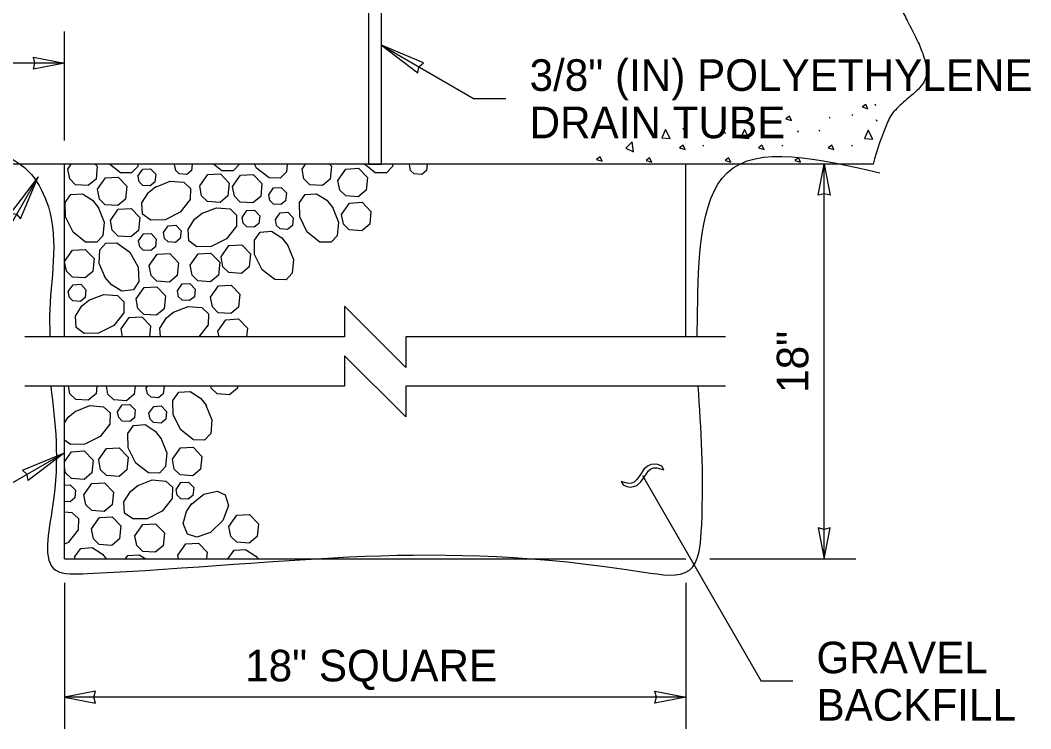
# Model space of a CAD drawing. Extents: x 99862 to 103151, y 100000 to 117076.
# Drawn here: x 101760 to 102272, y 109621 to 109980 of the extents above; entities that cross this region are included whole.
import ezdxf

# ---------------------------------------------------------------- set-up
doc = ezdxf.new("R2010")
doc.units = 0
for name, color, linetype in [('Level 11', 7, 'Continuous'), ('Level 14', 7, 'Continuous'), ('Level 15', 7, 'Continuous'), ('Level 18', 7, 'Continuous'), ('Level 20', 7, 'Continuous'), ('Level 29', 7, 'Continuous')]:
    doc.layers.add(name, color=color, linetype=linetype)

msp = doc.modelspace()

# ---------------------------------------------------------------- linework, layer by layer
at = {"layer": 'Level 11'}
for p, q in [((102191.96, 109906.89), (101636.86, 109906.89)), ((101782.16, 109819.39), (101782.16, 109906.89)), ((101936.38, 109906.89), (101942.94, 109906.89)), ((102097.16, 109819.39), (102097.16, 109906.89)), ((101782.16, 109706.89), (101782.16, 109794.39)), ((101782.16, 109706.89), (102097.16, 109706.89))]:
    msp.add_line(p, q, dxfattribs=at)
msp.add_spline([(102191.96, 110071.89), (102193.22, 110069.54), (102195.32, 110067.28), (102200.74, 110062.92), (102205.63, 110058.55), (102207.07, 110056.29), (102207.4, 110055.12), (102207.42, 110053.93), (102207.2, 110052.86), (102205.67, 110049.64), (102202.39, 110045.28), (102198.86, 110040.8), (102197.41, 110038.5), (102196.37, 110036.15), (102195.3, 110033.02), (102194.16, 110029.73), (102192.08, 110022.91), (102191.05, 110016.09), (102191.21, 110012.82), (102191.5, 110011.23), (102191.96, 110009.7), (102195.13, 110002.95), (102199.2, 109996.43), (102203.51, 109989.93), (102205.55, 109986.62), (102207.4, 109983.24), (102209.24, 109979.65), (102214.83, 109968.51), (102217.73, 109961.06), (102218.67, 109957.4), (102218.97, 109955.61), (102219.08, 109954.72), (102219.16, 109953.84), (102216.82, 109947.2), (102210.8, 109941.21), (102204, 109935.1), (102201.21, 109931.76), (102199.31, 109928.11), (102191.96, 109906.89)], degree=3, dxfattribs=at)
at = {"layer": 'Level 14'}
for p, q in [((101936.38, 109906.89), (101936.38, 110019.39)), ((101942.94, 109906.89), (101942.94, 110019.39))]:
    msp.add_line(p, q, dxfattribs=at)
at = {"layer": 'Level 15'}
for p, q in [((101782.16, 109918.89), (101782.16, 109974.04)), ((101942.94, 109967.12), (101989.9, 109940.01)), ((101782.16, 109958.04), (101677.98, 109958.04)), ((102005.9, 109940.01), (101989.9, 109940.01)), ((102167.16, 109706.89), (102167.16, 109906.89)), ((101768.82, 109900.41), (101734.16, 109840.38)), ((101782.16, 109760.64), (101725.87, 109728.14)), ((102079.51, 109754.79), (102077.98, 109754.14)), ((102081.12, 109754.97), (102079.51, 109754.79)), ((102082.87, 109754.7), (102081.12, 109754.97)), ((102084.89, 109753.95), (102082.87, 109754.7)), ((102076.05, 109752.6), (102073.78, 109749.2)), ((102074.32, 109745.95), (102076.84, 109749.57)), ((102077.98, 109754.14), (102076.05, 109752.6)), ((102076.84, 109749.57), (102078.22, 109751.56)), ((102078.22, 109751.56), (102079.38, 109752.51)), ((102079.38, 109752.51), (102080.72, 109752.99)), ((102080.72, 109752.99), (102082.37, 109753.05)), ((102082.37, 109753.05), (102085.94, 109752.12)), ((102085.94, 109752.12), (102084.89, 109753.95)), ((102066.56, 109745.48), (102064.25, 109746.22)), ((102064.25, 109746.22), (102065.31, 109744.39)), ((102065.31, 109744.39), (102067.14, 109743.62)), ((102068.27, 109745.21), (102066.56, 109745.48)), ((102069.63, 109745.36), (102068.27, 109745.21)), ((102070.86, 109745.85), (102069.63, 109745.36)), ((102072.32, 109747.11), (102070.86, 109745.85)), ((102072.23, 109744.2), (102074.32, 109745.95)), ((102073.78, 109749.2), (102072.32, 109747.11)), ((102075.14, 109749.18), (102135.28, 109645.01)), ((102067.14, 109743.62), (102068.91, 109743.33)), ((102068.91, 109743.33), (102070.61, 109743.53)), ((102070.61, 109743.53), (102072.23, 109744.2)), ((102109.16, 109706.89), (102183.16, 109706.89)), ((101782.16, 109694.89), (101782.16, 109620.89)), ((102097.16, 109694.89), (102097.16, 109620.89)), ((102151.28, 109645.01), (102135.28, 109645.01)), ((102097.16, 109636.89), (101782.16, 109636.89))]:
    msp.add_line(p, q, dxfattribs=at)
for points in [[(101942.94, 109967.12), (101961.22, 109953.12), (101961.8, 109956.23), (101964.21, 109958.29)], [(101782.16, 109958.04), (101766.44, 109954.96), (101767.17, 109958.04), (101766.44, 109961.12)], [(102167.16, 109906.89), (102170.25, 109891.17), (102167.16, 109891.89), (102164.08, 109891.17)], [(101768.82, 109900.41), (101754.82, 109882.13), (101757.93, 109881.56), (101759.99, 109879.15)], [(101782.16, 109760.64), (101763.88, 109746.64), (101763.31, 109749.75), (101760.9, 109751.81)], [(102167.16, 109706.89), (102170.25, 109722.62), (102167.16, 109721.89), (102164.08, 109722.62)], [(101782.16, 109636.89), (101797.89, 109633.81), (101797.16, 109636.89), (101797.89, 109639.97)], [(102097.16, 109636.89), (102081.44, 109633.81), (102082.17, 109636.89), (102081.44, 109639.97)]]:
    msp.add_lwpolyline(points, close=True, dxfattribs=at)
for points in [[(102117.16, 109819.39), (101955.15, 109819.39), (101955.15, 109803.9), (101924.18, 109834.88), (101924.18, 109819.39), (101762.16, 109819.39)], [(102117.16, 109794.39), (101955.15, 109794.39), (101955.15, 109778.9), (101924.18, 109809.88), (101924.18, 109794.39), (101762.16, 109794.39)]]:
    msp.add_lwpolyline(points, dxfattribs=at)
at = {"layer": 'Level 18'}
for p, q in [((102193.43, 109936.43), (102193.07, 109937.23)), ((102170.21, 109929.93), (102169.86, 109930.73)), ((102181.47, 109932.08), (102181.12, 109931.55)), ((102194.11, 109928.49), (102193.75, 109929.29)), ((102096.12, 109924.27), (102095.76, 109925.07)), ((102154.19, 109922.95), (102153.84, 109923.75)), ((102164.79, 109924.17), (102164.43, 109923.64)), ((102117.16, 109922.23), (102116.81, 109923.03)), ((102106.06, 109916.55), (102105.71, 109916.01)), ((102146.06, 109916.55), (102145.71, 109916.01)), ((102181.44, 109916.55), (102181.08, 109916.01))]:
    msp.add_line(p, q, dxfattribs=at)
for points in [[(102189.36, 109934.96), (102188.3, 109937.18), (102186.52, 109935.85), (102189.36, 109934.96)], [(102150.66, 109928.93), (102149.6, 109931.15), (102147.82, 109929.82), (102150.66, 109928.93)], [(102089.15, 109919.83), (102086.75, 109924.36), (102084.89, 109920.19), (102089.06, 109919.83)], [(102129.15, 109919.83), (102126.75, 109924.36), (102124.89, 109920.19), (102129.06, 109919.83)], [(102191.89, 109919.51), (102189.49, 109924.04), (102187.63, 109919.86), (102191.8, 109919.51)], [(102070.61, 109913.12), (102069.91, 109918.19), (102066.73, 109914.91), (102070.53, 109913.15)], [(102096.74, 109914.24), (102095.67, 109916.46), (102093.9, 109915.12), (102096.74, 109914.24)], [(102136.74, 109914.24), (102135.67, 109916.46), (102133.9, 109915.12), (102136.74, 109914.24)], [(102172.11, 109914.24), (102171.05, 109916.46), (102169.27, 109915.12), (102172.11, 109914.24)], [(102054.74, 109908.35), (102053.67, 109910.57), (102051.89, 109909.24), (102054.74, 109908.35)], [(102079.81, 109907.89), (102078.74, 109910.11), (102076.97, 109908.78), (102079.81, 109907.89)], [(102119.81, 109907.89), (102118.74, 109910.11), (102116.97, 109908.78), (102119.81, 109907.89)], [(102155.18, 109907.89), (102154.12, 109910.11), (102152.34, 109908.78), (102155.18, 109907.89)], [(101783.9, 109904.37), (101785.67, 109906.89)], [(101797.83, 109906.89), (101798.85, 109905.83), (101798.2, 109899.32), (101794.22, 109896.02), (101787.86, 109896.48), (101784.87, 109899.38), (101783.9, 109904.36)], [(101819.44, 109906.89), (101819.34, 109905.76), (101816.21, 109902.47), (101810.59, 109902.57), (101805.07, 109906.89)], [(101819.47, 109900.87), (101821.89, 109904.31), (101825.76, 109904.53), (101828.44, 109901.75), (101828.06, 109897.84), (101825.67, 109895.86), (101821.85, 109896.13), (101820.06, 109897.87), (101819.48, 109900.87)], [(101838, 109906.69), (101838.15, 109906.89)], [(101846.91, 109906.89), (101846.59, 109903.66), (101844.2, 109901.68), (101840.38, 109901.95), (101838.59, 109903.69), (101838.01, 109906.69)], [(101870.77, 109906.89), (101870.76, 109906.74), (101867.62, 109903.44), (101862, 109903.55), (101857.73, 109906.89)], [(101895, 109906.89), (101894.67, 109903.08), (101891.54, 109899.78), (101885.92, 109899.89), (101879.52, 109904.89), (101878.52, 109906.89)], [(101902.62, 109904.37), (101904.39, 109906.89)], [(101916.55, 109906.89), (101917.57, 109905.83), (101916.92, 109899.32), (101912.94, 109896.02), (101906.58, 109896.48), (101903.59, 109899.38), (101902.62, 109904.36)], [(101920.75, 109898.67), (101924.79, 109904.41), (101931.23, 109904.78), (101935.7, 109900.13), (101935.06, 109893.63), (101931.08, 109890.32), (101924.72, 109890.78), (101921.73, 109893.68), (101920.76, 109898.67)], [(101948.58, 109906.89), (101948.48, 109905.76), (101945.35, 109902.47), (101939.73, 109902.57), (101934.21, 109906.89)], [(101957.04, 109906.69), (101957.18, 109906.89)], [(101965.94, 109906.89), (101965.62, 109903.66), (101963.23, 109901.68), (101959.41, 109901.95), (101957.62, 109903.69), (101957.04, 109906.69)], [(102076.57, 109906.69), (102076.72, 109906.89)], [(101798.91, 109894.21), (101802.94, 109899.95), (101809.38, 109900.32), (101813.86, 109895.67), (101813.21, 109889.17), (101809.24, 109885.86), (101802.88, 109886.32), (101799.88, 109889.22), (101798.91, 109894.21)], [(101828.26, 109895.3), (101835.8, 109898.29), (101842.74, 109897.69), (101846.03, 109894.56), (101845.93, 109888.94), (101840.92, 109882.55), (101833.2, 109878.68), (101825.92, 109878.55), (101821.81, 109881.47), (101821.43, 109887.27), (101824.75, 109892.45), (101828.56, 109895.49)], [(101850.76, 109895.83), (101854.79, 109901.57), (101861.23, 109901.93), (101865.71, 109897.29), (101865.06, 109890.79), (101861.08, 109887.48), (101854.72, 109887.94), (101851.73, 109890.84), (101850.76, 109895.82)], [(101867.35, 109895.58), (101871.38, 109901.32), (101877.82, 109901.69), (101882.3, 109897.04), (101881.66, 109890.54), (101877.67, 109887.23), (101871.32, 109887.69), (101868.33, 109890.59), (101867.35, 109895.58)], [(101885.71, 109891.4), (101888.12, 109894.84), (101891.99, 109895.06), (101894.68, 109892.28), (101894.29, 109888.38), (101891.9, 109886.39), (101888.08, 109886.67), (101886.29, 109888.41), (101885.71, 109891.4)], [(101799.31, 109885.1), (101802.3, 109877.56), (101801.7, 109870.62), (101798.57, 109867.33), (101792.94, 109867.43), (101786.55, 109872.44), (101782.69, 109880.16), (101782.56, 109887.44), (101785.47, 109891.54), (101791.27, 109891.93), (101796.46, 109888.61), (101799.5, 109884.8)], [(101918.03, 109885.1), (101921.02, 109877.56), (101920.42, 109870.62), (101917.29, 109867.33), (101911.66, 109867.43), (101905.27, 109872.44), (101901.41, 109880.16), (101901.28, 109887.44), (101904.19, 109891.54), (101910, 109891.93), (101915.18, 109888.61), (101918.22, 109884.8)], [(101805.46, 109878.38), (101809.49, 109884.12), (101815.94, 109884.49), (101820.41, 109879.85), (101819.76, 109873.34), (101815.79, 109870.03), (101809.43, 109870.49), (101806.43, 109873.39), (101805.46, 109878.38)], [(101851.67, 109881.82), (101859.22, 109884.81), (101866.15, 109884.21), (101869.44, 109881.08), (101869.34, 109875.46), (101864.34, 109869.06), (101856.61, 109865.2), (101849.33, 109865.07), (101845.23, 109867.99), (101844.84, 109873.79), (101848.16, 109878.98), (101851.97, 109882.01)], [(101872.18, 109879.91), (101874.6, 109883.35), (101878.47, 109883.57), (101881.15, 109880.79), (101880.77, 109876.88), (101878.38, 109874.9), (101874.56, 109875.18), (101872.77, 109876.92), (101872.19, 109879.91)], [(101922.57, 109881.46), (101926.61, 109887.2), (101933.05, 109887.56), (101937.52, 109882.92), (101936.88, 109876.42), (101932.9, 109873.11), (101926.54, 109873.57), (101923.55, 109876.47), (101922.58, 109881.46)], [(101889.11, 109878.87), (101891.53, 109882.31), (101895.39, 109882.53), (101898.08, 109879.74), (101897.69, 109875.84), (101895.31, 109873.86), (101891.49, 109874.13), (101889.69, 109875.87), (101889.11, 109878.86)], [(101832.32, 109872.25), (101834.74, 109875.69), (101838.6, 109875.91), (101841.29, 109873.13), (101840.9, 109869.22), (101838.51, 109867.24), (101834.7, 109867.51), (101832.9, 109869.25), (101832.32, 109872.25)], [(101895.2, 109866.07), (101898.2, 109858.52), (101897.6, 109851.59), (101894.47, 109848.29), (101888.84, 109848.4), (101882.45, 109853.4), (101878.59, 109861.13), (101878.46, 109868.41), (101881.37, 109872.51), (101887.17, 109872.9), (101892.36, 109869.57), (101895.4, 109865.76)], [(101819.78, 109868.09), (101822.2, 109871.53), (101826.07, 109871.75), (101828.75, 109868.97), (101828.37, 109865.06), (101825.98, 109863.08), (101822.16, 109863.35), (101820.37, 109865.09), (101819.79, 109868.09)], [(101782.29, 109857.6), (101786.33, 109863.34), (101792.77, 109863.71), (101797.24, 109859.07), (101796.6, 109852.56), (101792.62, 109849.25), (101786.26, 109849.71), (101783.27, 109852.61), (101782.3, 109857.6)], [(101803.07, 109849.15), (101799.81, 109856.58), (101800.16, 109863.53), (101803.17, 109866.93), (101808.8, 109867.03), (101815.36, 109862.26), (101819.5, 109854.68), (101819.89, 109847.41), (101817.12, 109843.21), (101811.34, 109842.61), (101806.04, 109845.75), (101802.86, 109849.45)], [(101861.55, 109859.92), (101865.58, 109865.66), (101872.03, 109866.03), (101876.5, 109861.38), (101875.86, 109854.88), (101871.88, 109851.57), (101865.52, 109852.03), (101862.53, 109854.93), (101861.56, 109859.92)], [(101825.1, 109855.48), (101829.13, 109861.21), (101835.57, 109861.58), (101840.05, 109856.94), (101839.4, 109850.43), (101835.42, 109847.12), (101829.06, 109847.59), (101826.07, 109850.49), (101825.1, 109855.47)], [(101845.91, 109855.71), (101849.94, 109861.45), (101856.38, 109861.82), (101860.86, 109857.18), (101860.21, 109850.67), (101856.23, 109847.36), (101849.87, 109847.82), (101846.88, 109850.72), (101845.91, 109855.71)], [(101784.13, 109842.36), (101786.55, 109845.8), (101790.42, 109846.02), (101793.1, 109843.24), (101792.71, 109839.33), (101790.33, 109837.35), (101786.51, 109837.62), (101784.72, 109839.37), (101784.13, 109842.36)], [(101818.48, 109838.67), (101822.52, 109844.41), (101828.95, 109844.78), (101833.43, 109840.14), (101832.79, 109833.63), (101828.81, 109830.32), (101822.45, 109830.79), (101819.46, 109833.69), (101818.48, 109838.67)], [(101839.44, 109842.75), (101841.86, 109846.19), (101845.72, 109846.41), (101848.41, 109843.62), (101848.02, 109839.72), (101845.64, 109837.74), (101841.82, 109838.01), (101840.02, 109839.75), (101839.44, 109842.74)], [(101856.18, 109839.55), (101860.21, 109845.29), (101866.65, 109845.65), (101871.13, 109841.01), (101870.48, 109834.51), (101866.5, 109831.2), (101860.14, 109831.66), (101857.15, 109834.56), (101856.18, 109839.55)], [(101794.58, 109837.94), (101802.13, 109840.93), (101809.06, 109840.33), (101812.36, 109837.2), (101812.25, 109831.58), (101807.25, 109825.18), (101799.52, 109821.32), (101792.24, 109821.19), (101788.14, 109824.11), (101787.75, 109829.9), (101791.08, 109835.09), (101794.89, 109838.13)], [(101830.85, 109819.39), (101830.55, 109823.81), (101833.88, 109828.99), (101837.69, 109832.03)], [(101837.38, 109831.84), (101844.93, 109834.83), (101851.86, 109834.23), (101855.16, 109831.1), (101855.05, 109825.47), (101850.29, 109819.39)], [(101810.89, 109823.49), (101814.93, 109829.23), (101821.36, 109829.6), (101825.84, 109824.96), (101825.29, 109819.39)], [(101859.97, 109822.37), (101864, 109828.11), (101870.44, 109828.47), (101874.92, 109823.83), (101874.48, 109819.39)], [(101811.69, 109819.39), (101810.89, 109823.49)], [(101860.56, 109819.39), (101859.97, 109822.37)], [(101798.64, 109794.39), (101798.26, 109790.58), (101794.28, 109787.27), (101787.92, 109787.73), (101784.93, 109790.63), (101784.2, 109794.39)], [(101817.95, 109794.39), (101817.55, 109790.33), (101813.56, 109787.02), (101807.21, 109787.49), (101804.22, 109790.39), (101803.44, 109794.39)], [(101823.69, 109793.6), (101824.24, 109794.39)], [(101832.65, 109794.39), (101832.27, 109790.58), (101829.88, 109788.59), (101826.06, 109788.87), (101824.27, 109790.61), (101823.69, 109793.6)], [(101853.92, 109784.89), (101856.91, 109777.35), (101856.31, 109770.42), (101853.18, 109767.12), (101847.55, 109767.23), (101841.16, 109772.23), (101837.3, 109779.95), (101837.17, 109787.24), (101840.08, 109791.33), (101845.89, 109791.72), (101851.07, 109788.4), (101854.11, 109784.59)], [(101869.95, 109794.39), (101869.86, 109793.42), (101865.88, 109790.11), (101859.52, 109790.57), (101856.53, 109793.47), (101856.35, 109794.39)], [(101787.56, 109781.61), (101795.11, 109784.61), (101802.04, 109784.01), (101805.33, 109780.87), (101805.23, 109775.25), (101800.23, 109768.86), (101792.5, 109764.99), (101785.22, 109764.87), (101782.16, 109767.04)], [(101782.16, 109775.82), (101784.05, 109778.77), (101787.86, 109781.81)], [(101809.11, 109781.49), (101811.53, 109784.94), (101815.39, 109785.16), (101818.08, 109782.37), (101817.69, 109778.47), (101815.3, 109776.48), (101811.49, 109776.76), (101809.69, 109778.5), (101809.11, 109781.49)], [(101825, 109780.73), (101827.42, 109784.17), (101831.28, 109784.4), (101833.97, 109781.61), (101833.58, 109777.71), (101831.2, 109775.72), (101827.38, 109776), (101825.58, 109777.74), (101825, 109780.73)], [(101831.09, 109768.13), (101834.09, 109760.59), (101833.49, 109753.66), (101830.36, 109750.36), (101824.73, 109750.47), (101818.34, 109755.47), (101814.48, 109763.2), (101814.35, 109770.48), (101817.26, 109774.58), (101823.06, 109774.97), (101828.25, 109771.64), (101831.29, 109767.83)], [(101782.16, 109756.03), (101785.83, 109761.24), (101792.27, 109761.61), (101796.75, 109756.97), (101796.1, 109750.46), (101792.12, 109747.15), (101785.76, 109747.62), (101782.77, 109750.52), (101782.16, 109753.65)], [(101799.53, 109757.06), (101803.56, 109762.8), (101810.01, 109763.17), (101814.48, 109758.53), (101813.84, 109752.02), (101809.86, 109748.71), (101803.5, 109749.17), (101800.51, 109752.08), (101799.54, 109757.06)], [(101836.9, 109757.4), (101840.94, 109763.13), (101847.38, 109763.5), (101851.86, 109758.86), (101851.21, 109752.36), (101847.23, 109749.05), (101840.87, 109749.51), (101837.88, 109752.41), (101836.91, 109757.4)], [(101782.16, 109744.32), (101785.13, 109744.49), (101787.82, 109741.7), (101787.43, 109737.8), (101785.04, 109735.82), (101782.16, 109736.03)], [(101792.07, 109739.34), (101796.1, 109745.08), (101802.54, 109745.44), (101807.02, 109740.8), (101806.37, 109734.3), (101802.39, 109730.99), (101796.03, 109731.45), (101793.04, 109734.35), (101792.07, 109739.34)], [(101819.13, 109743.93), (101826.68, 109746.92), (101833.61, 109746.32), (101836.9, 109743.19), (101836.8, 109737.56), (101831.8, 109731.17), (101824.07, 109727.31), (101816.79, 109727.18), (101812.69, 109730.09), (101812.3, 109735.89), (101815.63, 109741.08), (101819.44, 109744.12)], [(101838.74, 109742.15), (101841.16, 109745.59), (101845.03, 109745.81), (101847.71, 109743.03), (101847.33, 109739.13), (101844.94, 109737.14), (101841.12, 109737.42), (101839.33, 109739.16), (101838.75, 109742.15)], [(101846.52, 109734.65), (101852.81, 109739.77), (101859.6, 109741.3), (101863.69, 109739.31), (101865.28, 109733.91), (101862.44, 109726.31), (101856.25, 109720.29), (101849.34, 109717.97), (101844.55, 109719.51), (101842.43, 109724.93), (101844.04, 109730.88), (101846.75, 109734.92)], [(101782.16, 109730.78), (101785.95, 109730.45), (101789.24, 109727.32), (101789.14, 109721.7), (101784.13, 109715.31), (101782.16, 109714.32)], [(101865.5, 109723.29), (101869.54, 109729.02), (101875.98, 109729.39), (101880.46, 109724.75), (101879.81, 109718.25), (101875.83, 109714.94), (101869.47, 109715.4), (101866.48, 109718.3), (101865.51, 109723.29)], [(101795.86, 109722.16), (101799.89, 109727.9), (101806.33, 109728.27), (101810.81, 109723.62), (101810.16, 109717.12), (101806.18, 109713.81), (101799.83, 109714.27), (101796.84, 109717.17), (101795.86, 109722.16)], [(101817.91, 109718.65), (101821.95, 109724.38), (101828.39, 109724.75), (101832.86, 109720.11), (101832.22, 109713.61), (101828.24, 109710.3), (101821.88, 109710.76), (101818.89, 109713.66), (101817.92, 109718.64)], [(101839.64, 109708.89), (101843.67, 109714.63), (101850.11, 109714.99), (101854.59, 109710.35), (101854.24, 109706.89)], [(101787.53, 109706.89), (101787.51, 109708.16), (101790.42, 109712.26), (101796.22, 109712.64), (101801.41, 109709.32), (101803.35, 109706.89)], [(101813.12, 109706.89), (101814.34, 109708.6), (101820.13, 109708.98), (101823.41, 109706.89)], [(101840.03, 109706.89), (101839.64, 109708.89)], [(101865.24, 109706.89), (101865.23, 109707.18), (101868.15, 109711.28), (101873.95, 109711.67), (101879.14, 109708.34), (101880.29, 109706.89)]]:
    msp.add_lwpolyline(points, dxfattribs=at)
at = {"layer": 'Level 29'}
for points in [[(101677.98, 109901.63), (101765.42, 109901.63), (101774.05, 109885.24), (101774.69, 109829.94), (101774.86, 109819.39)], [(102102.82, 109819.39), (102103.03, 109832.49), (102118.05, 109902.51), (102195.42, 109902.51)], [(101775.25, 109794.39), (101776.21, 109733.55), (101777.89, 109701.18), (101793.87, 109699.5), (102075.85, 109700.3), (102098.87, 109701.18), (102105.11, 109724.03), (102103.31, 109794.39)]]:
    msp.add_spline(points, degree=3, dxfattribs=at)

# ---------------------------------------------------------------- texts
at = {"layer": 'Level 20'}
for s, rotation, p in [('3/8" (IN) POLYETHYLENE', 360, (102017.9, 109944.01)), ('DRAIN TUBE', 360, (102017.9, 109920.01)), ('18"', 90, (102159.16, 109791.02)), ('GRAVEL', 360, (102163.28, 109649.01)), ('BACKFILL', 360, (102163.28, 109625.01))]:
    msp.add_text(s, height=16, rotation=rotation, dxfattribs=at).set_placement(p)
msp.add_text('18" SQUARE', height=16, dxfattribs=at).set_placement((101873.78, 109644.89))

doc.saveas('drawing.dxf')
